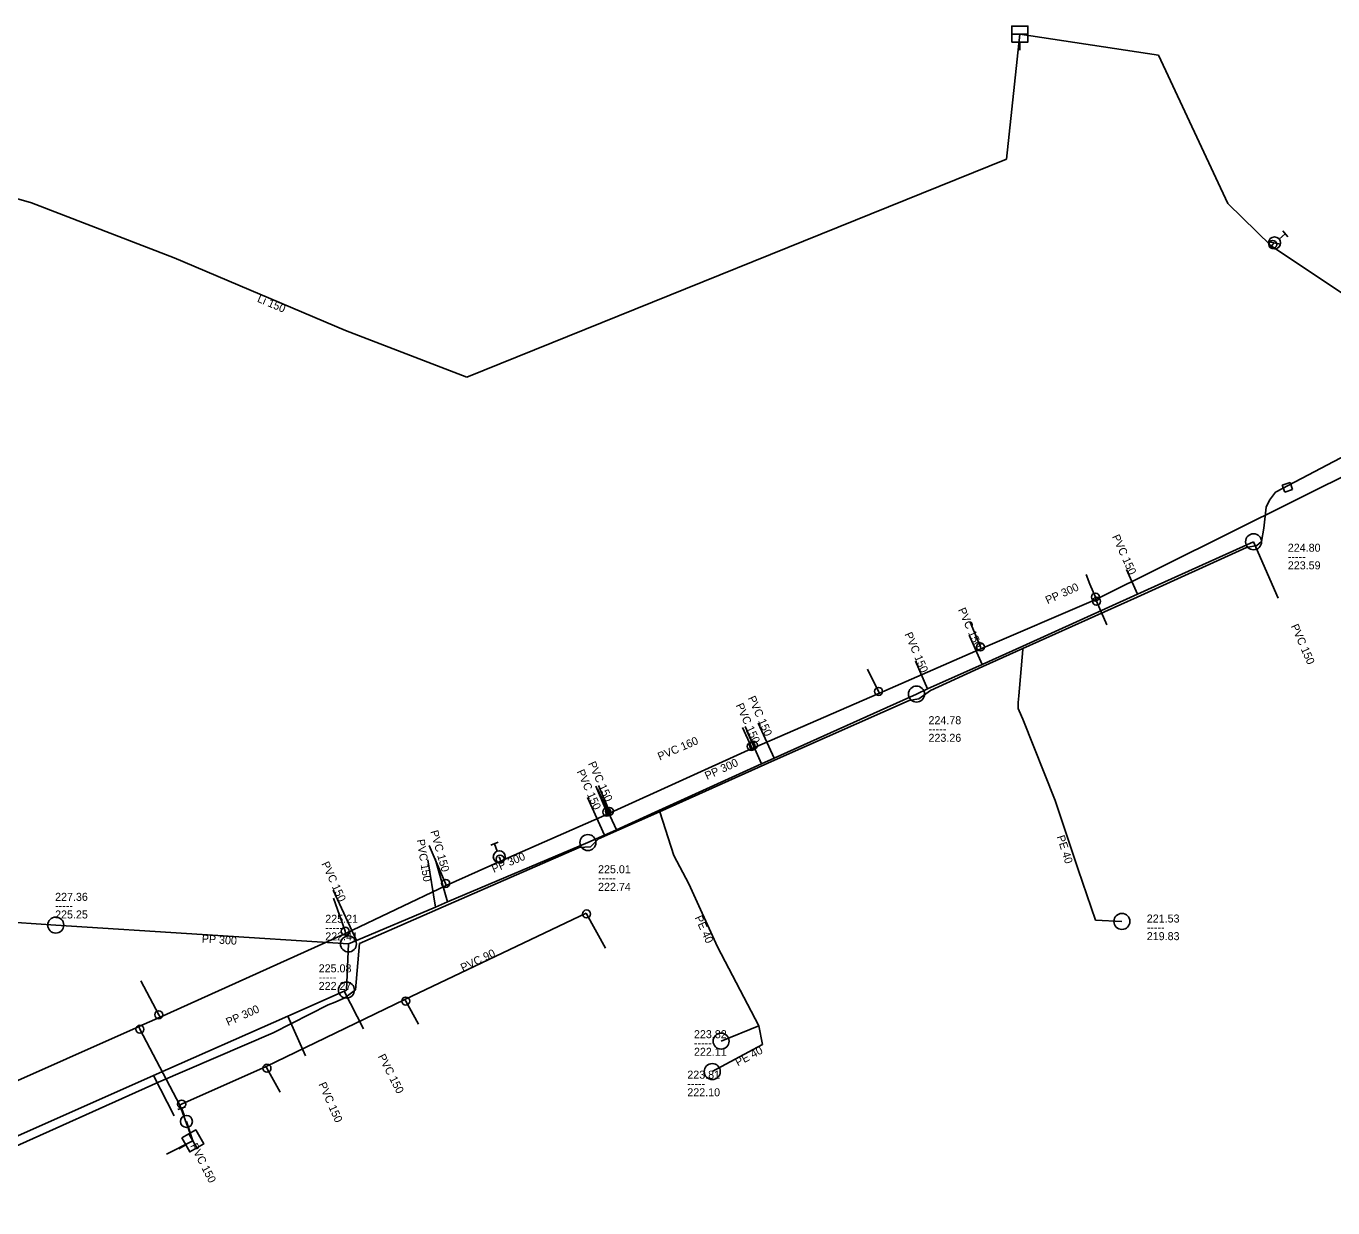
# Model space of a CAD drawing. Extents: x -771212 to -769571, y -1050452 to -1050119.
# Drawn here: x -770280.9 to -770117.6, y -1050279.7 to -1050132.1 of the extents above; entities that cross this region are included whole.
import ezdxf

# ---------------------------------------------------------------- set-up
doc = ezdxf.new("R2010")
doc.units = 0
doc.layers.add('Level 0', color=7, linetype='Continuous')

msp = doc.modelspace()

# ---------------------------------------------------------------- linework, layer by layer
at = {"layer": 'Level 0'}
for p, q in [((-770156.74, -1050133.07), (-770158.4, -1050148.69)), ((-770139.43, -1050135.68), (-770156.74, -1050133.07)), ((-770156.74, -1050135.07), (-770156.74, -1050134.07)), ((-770130.75, -1050154.22), (-770139.43, -1050135.68)), ((-770158.4, -1050148.69), (-770225.84, -1050175.95)), ((-770280.22, -1050154.16), (-770291.37, -1050150.94)), ((-770262.4, -1050161.03), (-770280.22, -1050154.16)), ((-770125.33, -1050159.5), (-770130.75, -1050154.22)), ((-770123.9, -1050157.64), (-770123.26, -1050158.41)), ((-770125.65, -1050159), (-770124.18, -1050159.31)), ((-770125.33, -1050159.5), (-770125.15, -1050159.35)), ((-770098.12, -1050177.82), (-770125.33, -1050159.5)), ((-770125.15, -1050159.35), (-770124.92, -1050159.15)), ((-770124.35, -1050158.67), (-770123.58, -1050158.03)), ((-770241, -1050170.09), (-770262.4, -1050161.03)), ((-770225.84, -1050175.95), (-770241, -1050170.09)), ((-770124.79, -1050190.31), (-770114.26, -1050184.77)), ((-770111.4, -1050185.86), (-770147.26, -1050203.69)), ((-770125.54, -1050191.28), (-770124.79, -1050190.31)), ((-770123.95, -1050189.43), (-770122.98, -1050189.08)), ((-770123.64, -1050190.31), (-770123.95, -1050189.43)), ((-770122.67, -1050189.96), (-770123.64, -1050190.31)), ((-770122.98, -1050189.08), (-770122.67, -1050189.96)), ((-770126.27, -1050194.78), (-770125.97, -1050192.16)), ((-770125.97, -1050192.16), (-770125.54, -1050191.28)), ((-770126.55, -1050196.47), (-770126.27, -1050194.78)), ((-770127.54, -1050196.49), (-770142.03, -1050203.03)), ((-770128.41, -1050197.21), (-770127.12, -1050196.98)), ((-770127.54, -1050196.49), (-770124.46, -1050203.53)), ((-770127.12, -1050196.98), (-770126.55, -1050196.47)), ((-770142.08, -1050203.41), (-770128.41, -1050197.21)), ((-770142.03, -1050203.03), (-770143.43, -1050199.94)), ((-770147.98, -1050201.79), (-770148.45, -1050200.58)), ((-770147.29, -1050203.4), (-770147.98, -1050201.79)), ((-770142.03, -1050203.03), (-770156.38, -1050209.52)), ((-770156.37, -1050209.83), (-770142.08, -1050203.41)), ((-770147.26, -1050203.69), (-770147.29, -1050203.4)), ((-770147.26, -1050203.69), (-770161.61, -1050209.87)), ((-770147.16, -1050203.93), (-770147.26, -1050203.69)), ((-770145.86, -1050206.88), (-770147.16, -1050203.93)), ((-770162.4, -1050207.82), (-770162.93, -1050206.55)), ((-770161.46, -1050211.82), (-770163.07, -1050208.17)), ((-770161.67, -1050209.63), (-770162.4, -1050207.82)), ((-770161.61, -1050209.87), (-770174.28, -1050215.42)), ((-770161.61, -1050209.87), (-770161.67, -1050209.63)), ((-770156.38, -1050209.52), (-770161.46, -1050211.82)), ((-770161.37, -1050212.07), (-770156.37, -1050209.83)), ((-770156.37, -1050209.95), (-770156.88, -1050215.75)), ((-770156.37, -1050209.83), (-770156.37, -1050209.95)), ((-770168.27, -1050214.89), (-770169.77, -1050211.4)), ((-770174.39, -1050215.19), (-770175.76, -1050212.42)), ((-770161.46, -1050211.82), (-770168.27, -1050214.89)), ((-770167.9, -1050215.07), (-770161.37, -1050212.07)), ((-770168.27, -1050214.89), (-770169.65, -1050215.52)), ((-770174.28, -1050215.42), (-770189.9, -1050222.19)), ((-770169.65, -1050215.52), (-770187.43, -1050223.55)), ((-770187.39, -1050223.79), (-770170.55, -1050216.34)), ((-770174.28, -1050215.42), (-770174.39, -1050215.19)), ((-770170.55, -1050216.34), (-770169.36, -1050216.1)), ((-770169.36, -1050216.1), (-770167.9, -1050215.07)), ((-770156.93, -1050216.57), (-770156.94, -1050217.33)), ((-770156.88, -1050215.75), (-770156.93, -1050216.57)), ((-770156.94, -1050217.33), (-770156.54, -1050218.3)), ((-770156.54, -1050218.3), (-770156.36, -1050218.65)), ((-770190.29, -1050222.06), (-770191.37, -1050219.72)), ((-770190.02, -1050221.91), (-770191.04, -1050219.58)), ((-770187.43, -1050223.55), (-770189.42, -1050219.14)), ((-770156.36, -1050218.65), (-770152.34, -1050228.81)), ((-770189, -1050224.26), (-770190.86, -1050220.13)), ((-770190.21, -1050222.32), (-770207.91, -1050230.38)), ((-770190.21, -1050222.32), (-770190.29, -1050222.06)), ((-770189.9, -1050222.19), (-770190.21, -1050222.32)), ((-770189.9, -1050222.19), (-770190.02, -1050221.91)), ((-770189, -1050224.26), (-770201.82, -1050230.07)), ((-770201.75, -1050230.22), (-770187.39, -1050223.79)), ((-770187.43, -1050223.55), (-770189, -1050224.26)), ((-770208.35, -1050230.26), (-770209.71, -1050227.05)), ((-770207.14, -1050232.48), (-770209.48, -1050227.37)), ((-770208.01, -1050230.18), (-770209.39, -1050226.93)), ((-770208.64, -1050233.15), (-770210.76, -1050228.46)), ((-770152.34, -1050228.81), (-770149.45, -1050237.44)), ((-770208.27, -1050230.54), (-770221.6, -1050236.4)), ((-770209.37, -1050233.63), (-770201.75, -1050230.22)), ((-770208.27, -1050230.54), (-770208.35, -1050230.26)), ((-770207.91, -1050230.38), (-770208.27, -1050230.54)), ((-770207.91, -1050230.38), (-770208.01, -1050230.18)), ((-770201.82, -1050230.07), (-770207.14, -1050232.48)), ((-770201.75, -1050230.22), (-770201.73, -1050230.25)), ((-770201.73, -1050230.25), (-770199.98, -1050235.68)), ((-770207.14, -1050232.48), (-770208.64, -1050233.15)), ((-770228.47, -1050239.18), (-770230.51, -1050234.45)), ((-770210.7, -1050234.08), (-770228.22, -1050241.5)), ((-770222.84, -1050234.39), (-770221.9, -1050234.04)), ((-770222.03, -1050235.16), (-770222.37, -1050234.22)), ((-770211.81, -1050234.71), (-770210.38, -1050234.6)), ((-770208.64, -1050233.15), (-770210.7, -1050234.08)), ((-770210.38, -1050234.6), (-770209.37, -1050233.63)), ((-770229.75, -1050242.15), (-770230.7, -1050236.22)), ((-770228.22, -1050241.5), (-770229.77, -1050236.1)), ((-770228.12, -1050241.82), (-770211.81, -1050234.71)), ((-770221.67, -1050236.14), (-770221.77, -1050235.86)), ((-770221.6, -1050236.4), (-770221.67, -1050236.14)), ((-770199.98, -1050235.68), (-770198.07, -1050239.22)), ((-770221.6, -1050236.4), (-770228.4, -1050239.43)), ((-770149.45, -1050237.44), (-770147.3, -1050243.78)), ((-770228.4, -1050239.43), (-770240.97, -1050245.42)), ((-770228.4, -1050239.43), (-770228.47, -1050239.18)), ((-770198.07, -1050239.22), (-770194.53, -1050247.09)), ((-770328.72, -1050240.89), (-770277.18, -1050244.39)), ((-770239.62, -1050246.33), (-770242.51, -1050240.03)), ((-770241.01, -1050245.16), (-770242.47, -1050241.01)), ((-770229.75, -1050242.15), (-770239.62, -1050246.33)), ((-770239.24, -1050246.7), (-770228.12, -1050241.82)), ((-770228.22, -1050241.5), (-770229.75, -1050242.15)), ((-770277.18, -1050244.39), (-770240.61, -1050246.75)), ((-770210.92, -1050242.9), (-770233.58, -1050253.7)), ((-770210.92, -1050242.9), (-770210.87, -1050242.99)), ((-770210.87, -1050242.99), (-770208.49, -1050247.26)), ((-770147.3, -1050243.78), (-770143.99, -1050243.93)), ((-770240.97, -1050245.42), (-770264.15, -1050255.89)), ((-770240.97, -1050245.42), (-770241.01, -1050245.16)), ((-770240.61, -1050246.75), (-770240.87, -1050252.51)), ((-770239.62, -1050246.33), (-770240.61, -1050246.75)), ((-770239.74, -1050252.48), (-770239.24, -1050246.7)), ((-770194.53, -1050247.09), (-770189.35, -1050256.96)), ((-770264.31, -1050255.59), (-770266.54, -1050251.35)), ((-770240.87, -1050252.51), (-770241.16, -1050252.64)), ((-770241.06, -1050253.48), (-770239.74, -1050252.48)), ((-770233.58, -1050253.7), (-770250.88, -1050262.04)), ((-770241.16, -1050252.64), (-770248.18, -1050255.76)), ((-770243.13, -1050254.35), (-770242.28, -1050254.02)), ((-770242.28, -1050254.02), (-770241.06, -1050253.48)), ((-770241.16, -1050252.64), (-770238.72, -1050257.36)), ((-770233.58, -1050253.7), (-770233.46, -1050253.88)), ((-770233.46, -1050253.88), (-770231.87, -1050256.76)), ((-770248.18, -1050255.76), (-770264.95, -1050263.2)), ((-770264.15, -1050255.89), (-770264.31, -1050255.59)), ((-770250.02, -1050257.87), (-770243.13, -1050254.35)), ((-770248.18, -1050255.76), (-770245.98, -1050260.74)), ((-770267.13, -1050257.23), (-770317.71, -1050279.72)), ((-770266.81, -1050257.08), (-770267.13, -1050257.23)), ((-770264.15, -1050255.89), (-770266.81, -1050257.08)), ((-770266.67, -1050257.4), (-770266.81, -1050257.08)), ((-770261.68, -1050266.88), (-770266.67, -1050257.4)), ((-770189.35, -1050256.96), (-770194.06, -1050258.89)), ((-770189.35, -1050256.96), (-770188.88, -1050259.32)), ((-770264.35, -1050264), (-770250.02, -1050257.87)), ((-770188.88, -1050259.32), (-770195.16, -1050262.69)), ((-770250.88, -1050262.04), (-770261.45, -1050266.76)), ((-770250.88, -1050262.04), (-770250.79, -1050262.27)), ((-770250.79, -1050262.27), (-770249.14, -1050265.28)), ((-770264.95, -1050263.2), (-770286.27, -1050272.66)), ((-770285.81, -1050273.65), (-770264.35, -1050264)), ((-770264.95, -1050263.2), (-770262.38, -1050268.22)), ((-770261.92, -1050267.45), (-770260.98, -1050267.1)), ((-770261.45, -1050266.76), (-770261.68, -1050266.88)), ((-770260.06, -1050271.35), (-770261.68, -1050266.88)), ((-770261.11, -1050268.22), (-770261.45, -1050267.28)), ((-770260.85, -1050268.92), (-770260.06, -1050271.35)), ((-770260.06, -1050271.35), (-770263.35, -1050273.03)), ((-770261.79, -1050272.35), (-770260.93, -1050271.85))]:
    msp.add_line(p, q, dxfattribs=at)
for points in [[(-770157.74, -1050133.07), (-770157.74, -1050132.07), (-770155.74, -1050132.07), (-770155.74, -1050133.07)], [(-770260.56, -1050270.48), (-770259.69, -1050269.98), (-770258.69, -1050271.72), (-770259.56, -1050272.22)]]:
    msp.add_lwpolyline(points, dxfattribs=at)
for points in [[(-770157.74, -1050134.07), (-770155.74, -1050134.07), (-770155.74, -1050133.07), (-770157.74, -1050133.07)], [(-770261.43, -1050270.98), (-770260.43, -1050272.72), (-770259.56, -1050272.22), (-770260.56, -1050270.48)]]:
    msp.add_lwpolyline(points, close=True, dxfattribs=at)
for centre, radius in [((-770124.92, -1050159.15), 0.75), ((-770125.15, -1050159.35), 0.5), ((-770127.54, -1050196.49), 1), ((-770147.29, -1050203.4), 0.5), ((-770147.16, -1050203.93), 0.5), ((-770161.67, -1050209.63), 0.5), ((-770174.39, -1050215.19), 0.5), ((-770169.65, -1050215.52), 1), ((-770190.29, -1050222.06), 0.5), ((-770190.02, -1050221.91), 0.5), ((-770208.01, -1050230.18), 0.5), ((-770208.35, -1050230.26), 0.5), ((-770210.7, -1050234.08), 1), ((-770221.77, -1050235.86), 0.75), ((-770221.67, -1050236.14), 0.5), ((-770228.47, -1050239.18), 0.5), ((-770210.87, -1050242.99), 0.5), ((-770277.18, -1050244.39), 1), ((-770143.99, -1050243.93), 1), ((-770240.61, -1050246.75), 1), ((-770241.01, -1050245.16), 0.5), ((-770240.87, -1050252.51), 1), ((-770233.46, -1050253.88), 0.5), ((-770264.31, -1050255.59), 0.5), ((-770266.67, -1050257.4), 0.5), ((-770194.06, -1050258.89), 1), ((-770250.79, -1050262.27), 0.5), ((-770195.16, -1050262.69), 1), ((-770261.45, -1050266.76), 0.5), ((-770260.85, -1050268.92), 0.75)]:
    msp.add_circle(centre, radius, dxfattribs=at)

# ---------------------------------------------------------------- texts
for s, rotation, p in [('Li 150', 337.054, (-770252.09, -1050166.48)), ('PVC 150', 294.374, (-770145.25, -1050195.85)), ('PP 300', 24.359, (-770153.27, -1050204.31)), ('PVC 150', 293.802, (-770164.49, -1050204.99)), ('PVC 150', 293.629, (-770122.91, -1050207.03)), ('PVC 150', 293.258, (-770171.17, -1050208.04)), ('PVC 150', 294.245, (-770192.25, -1050216.92)), ('PVC 150', 294.287, (-770190.74, -1050216.02)), ('PVC 160', 23.433, (-770201.72, -1050223.84)), ('PVC 150', 294.604, (-770210.7, -1050224.21)), ('PP 300', 24.38, (-770195.82, -1050226.25)), ('PVC 150', 294.324, (-770212.12, -1050225.21)), ('PVC 150', 286.015, (-770230.4, -1050232.69)), ('PVC 150', 279.102, (-770232.09, -1050233.74)), ('PE 40', 287.407, (-770152.13, -1050233.33)), ('PP 300', 23.018, (-770222.46, -1050237.88)), ('PVC 150', 294.642, (-770244.01, -1050236.72)), ('PE 40', 294.219, (-770197.38, -1050243.45)), ('PP 300', 356.308, (-770258.96, -1050246.57)), ('PVC 90', 25.738, (-770226.31, -1050250.23)), ('PP 300', 23.962, (-770255.65, -1050257.01)), ('PVC 150', 297.337, (-770236.97, -1050260.8)), ('PE 40', 28.219, (-770191.96, -1050262.06)), ('PVC 150', 293.834, (-770244.38, -1050264.27)), ('PVC 150', 297.11, (-770260.42, -1050271.95))]:
    msp.add_text(s, height=1, rotation=rotation, dxfattribs=at).set_placement(p)
for s, p in [('224.80', (-770123.26, -1050197.74)), ('-----', (-770123.26, -1050198.84)), ('223.59', (-770123.26, -1050199.94)), ('224.78', (-770168.15, -1050219.29)), ('-----', (-770168.15, -1050220.39)), ('223.26', (-770168.15, -1050221.49)), ('225.01', (-770209.43, -1050237.91)), ('-----', (-770209.43, -1050239.01)), ('222.74', (-770209.43, -1050240.11)), ('227.36', (-770277.26, -1050241.36)), ('-----', (-770277.26, -1050242.46)), ('225.25', (-770277.26, -1050243.56)), ('225.21', (-770243.51, -1050244.1)), ('221.53', (-770140.88, -1050244.07)), ('-----', (-770243.51, -1050245.2)), ('222.41', (-770243.51, -1050246.3)), ('-----', (-770140.88, -1050245.17)), ('219.83', (-770140.88, -1050246.27)), ('225.08', (-770244.33, -1050250.29)), ('-----', (-770244.33, -1050251.39)), ('222.27', (-770244.33, -1050252.49)), ('223.82', (-770197.45, -1050258.52)), ('-----', (-770197.45, -1050259.62)), ('222.11', (-770197.45, -1050260.72)), ('223.81', (-770198.28, -1050263.58)), ('-----', (-770198.28, -1050264.68)), ('222.10', (-770198.28, -1050265.78))]:
    msp.add_text(s, height=1, dxfattribs=at).set_placement(p)

doc.saveas('drawing.dxf')
